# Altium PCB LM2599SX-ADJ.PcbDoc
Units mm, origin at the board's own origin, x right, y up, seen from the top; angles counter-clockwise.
Board outline 62.86 x 68.58 mm, 2 copper layers (TopLayer, BottomLayer); 17 components, 8 nets, 38 pads, 5 vias.
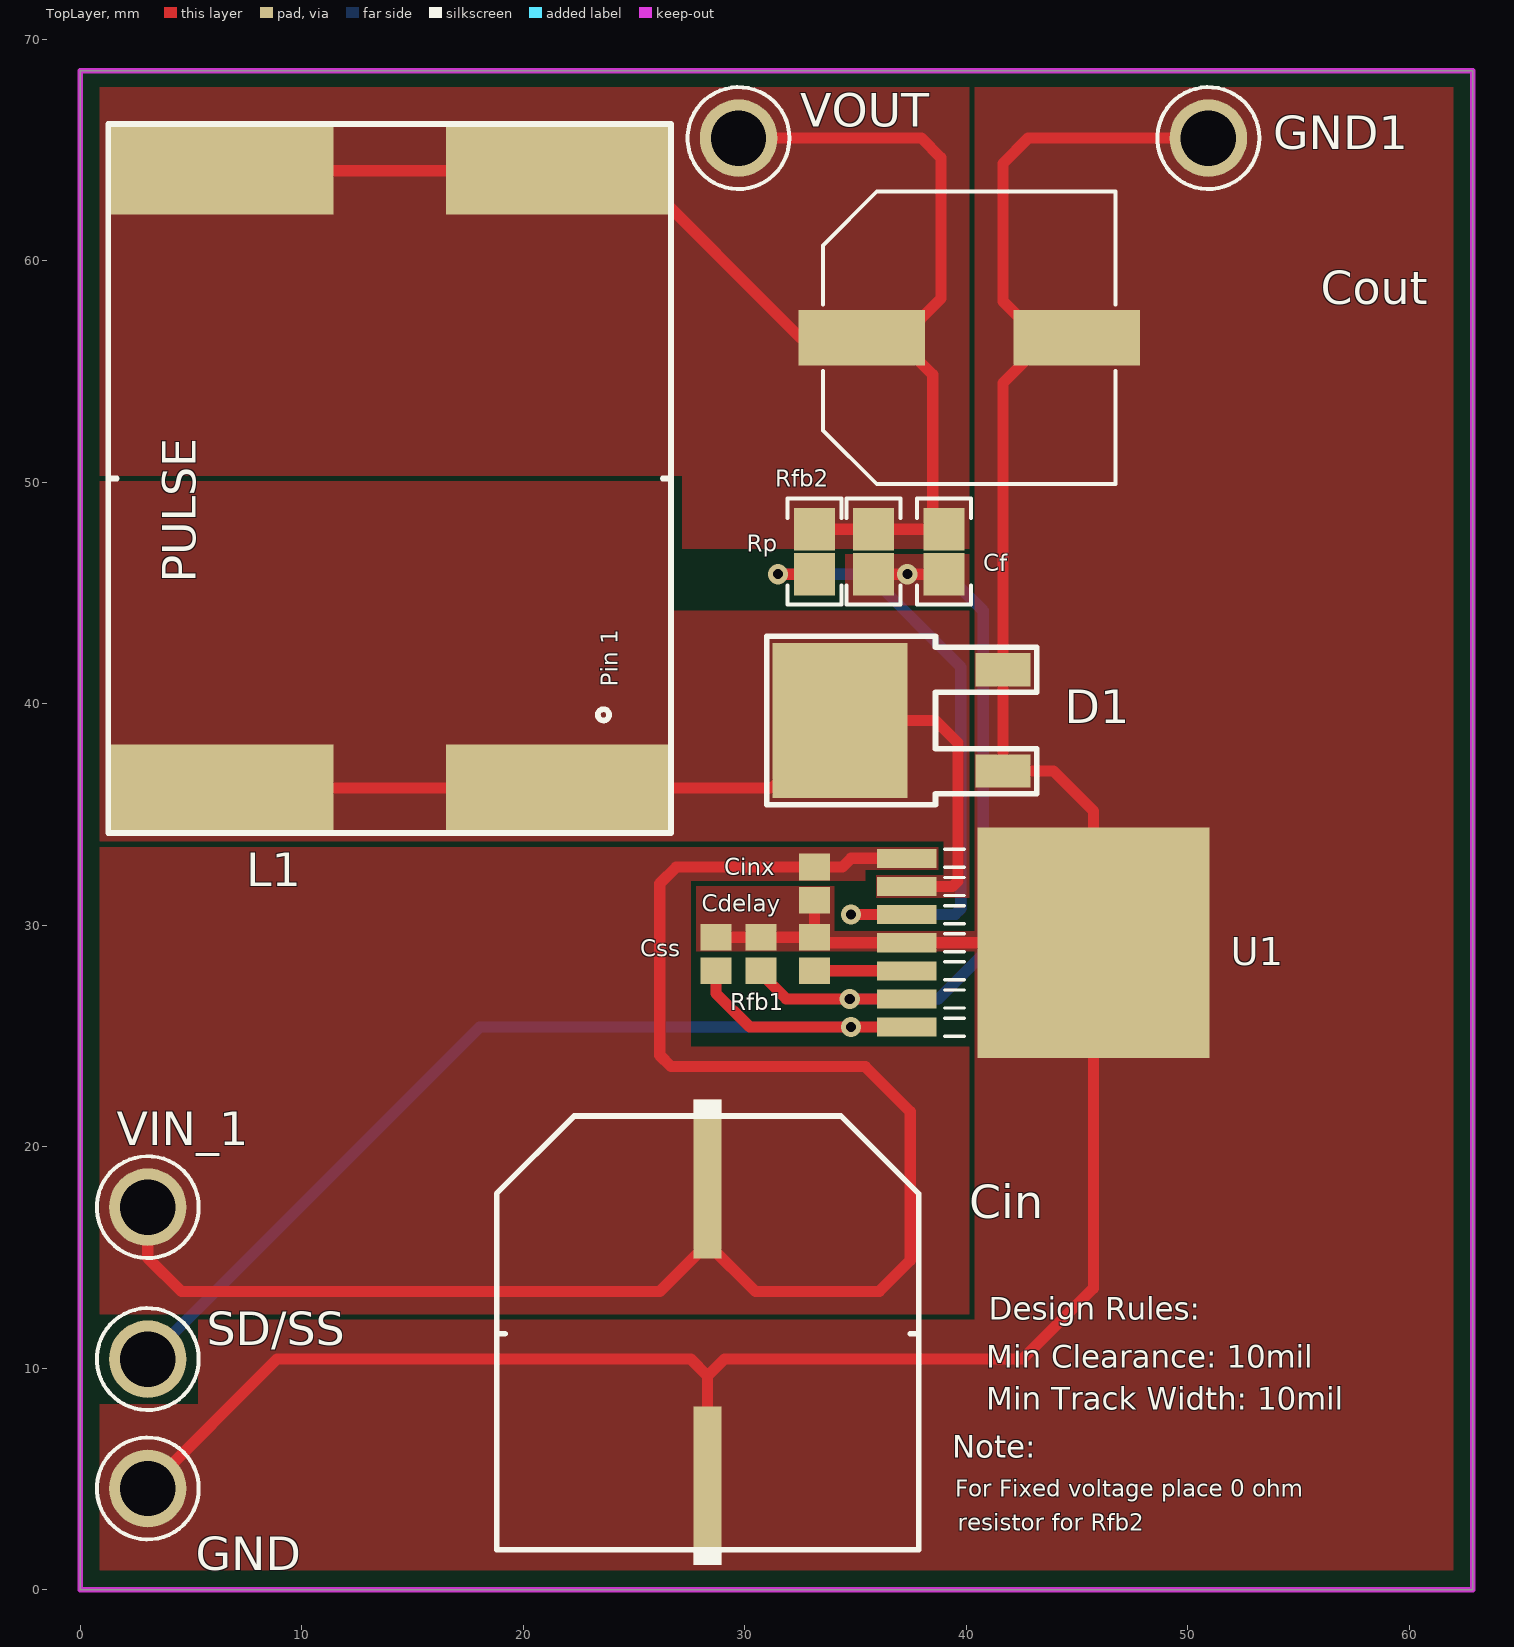
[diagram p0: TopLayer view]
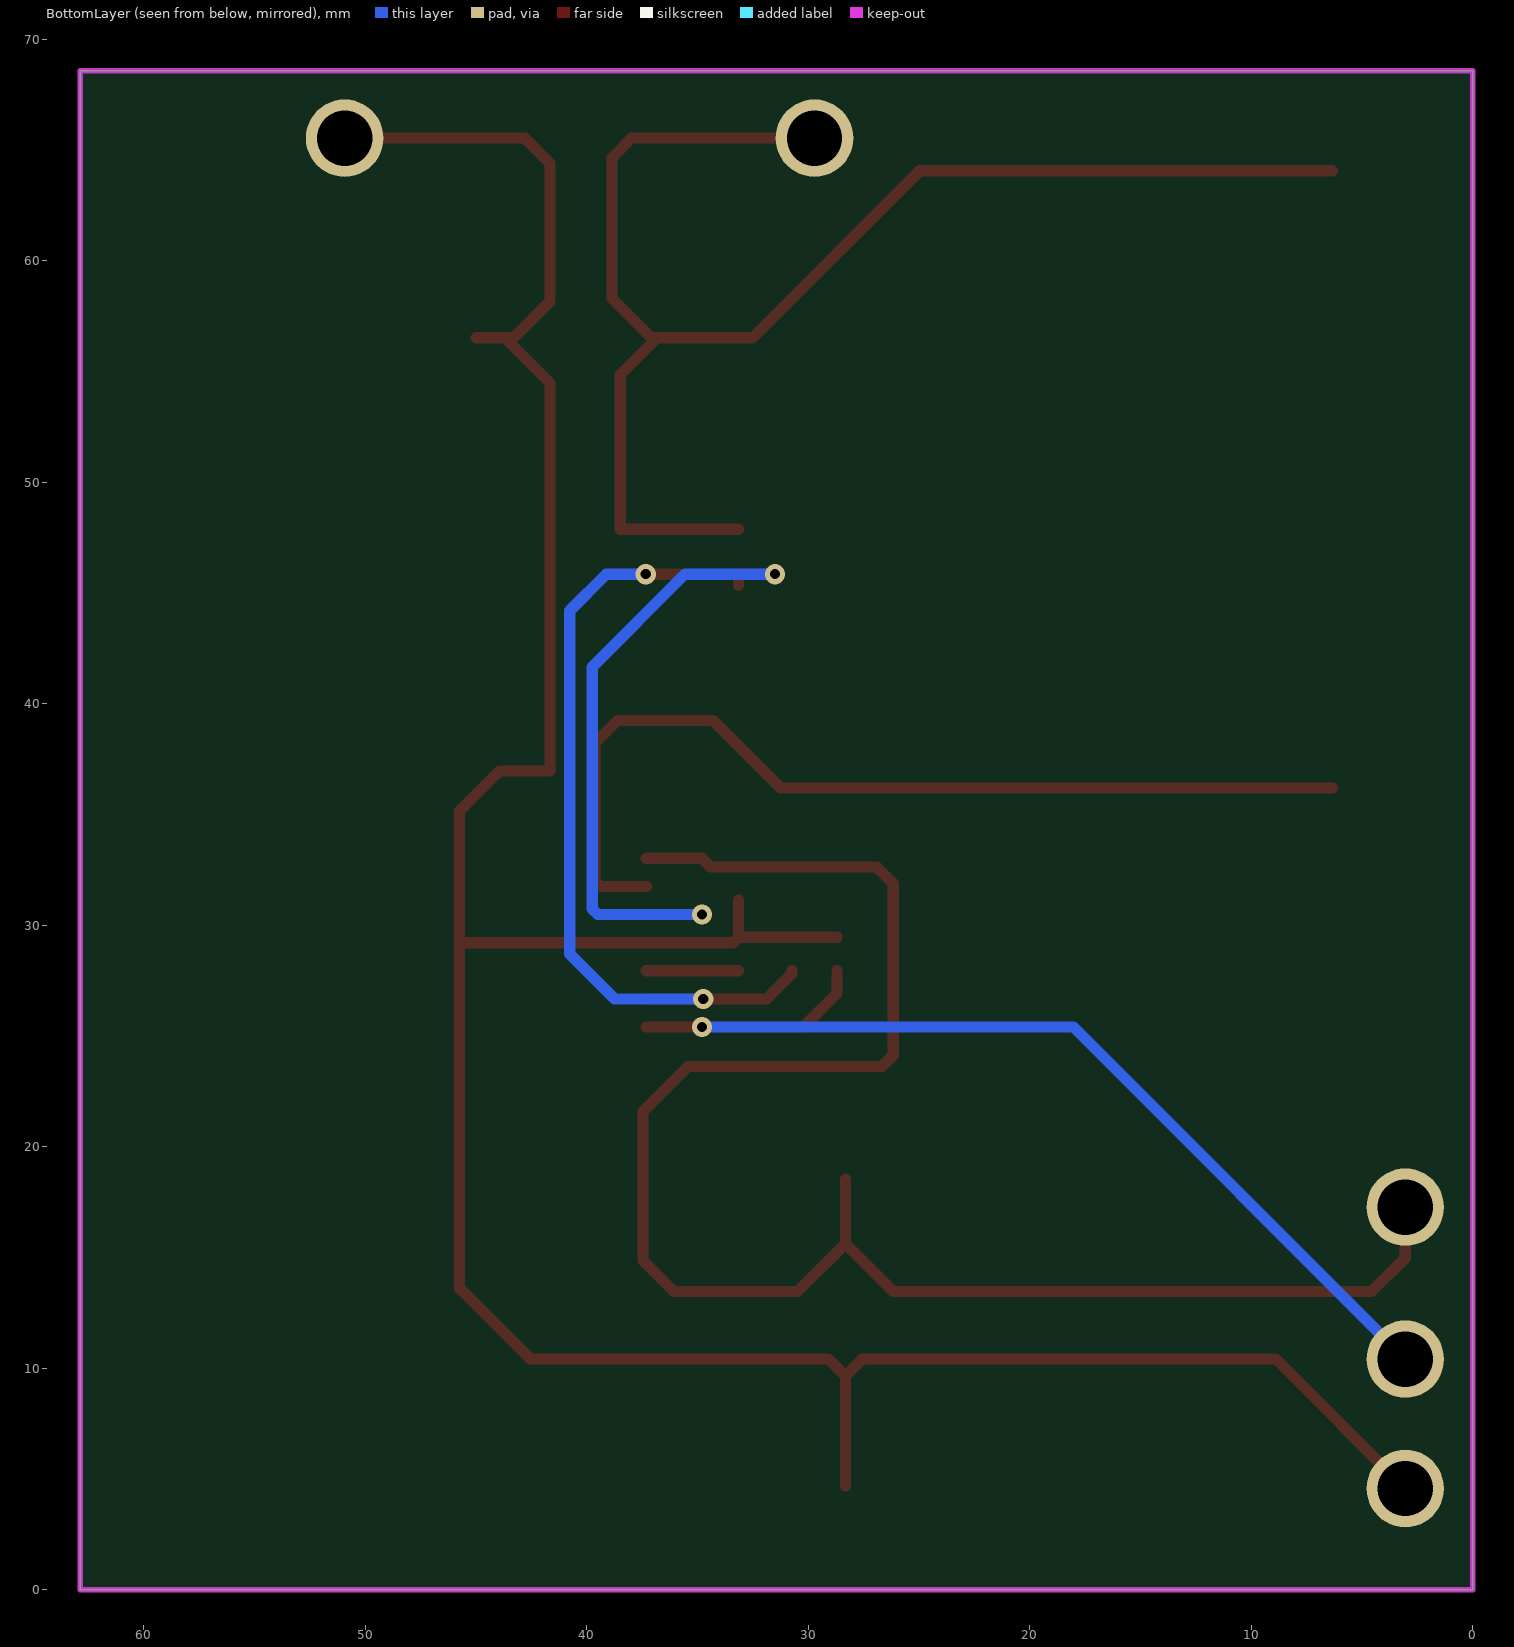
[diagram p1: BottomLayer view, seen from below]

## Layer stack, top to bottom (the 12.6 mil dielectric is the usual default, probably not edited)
TopSolder: solder mask 0.0102, Solder Resist, Dk 3.5
TopLayer: signal copper 0.0356
Dielectric1: core 0.32, FR-4, Dk 4.8
BottomLayer: signal copper 0.0356
BottomSolder: solder mask 0.0102, Solder Resist, Dk 3.5

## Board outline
0,0 0,68.58 62.865,68.58 62.865,0
cut-out: -118.11,-104.14 -117.856,-104.14 -117.856,-103.886 -118.11,-103.886
cut-out: -118.11,-104.14 -117.856,-104.14 -117.856,-103.886 -118.11,-103.886
cut-out: -118.11,-104.14 -117.856,-104.14 -117.856,-103.886 -118.11,-103.886
cut-out: -118.11,-104.14 -117.856,-104.14 -117.856,-103.886 -118.11,-103.886
cut-out: -118.11,-104.14 -117.856,-104.14 -117.856,-103.886 -118.11,-103.886
cut-out: -118.11,-104.14 -117.856,-104.14 -117.856,-103.886 -118.11,-103.886
cut-out: -118.11,-104.14 -117.856,-104.14 -117.856,-103.886 -118.11,-103.886
cut-out: -118.11,-104.14 -117.856,-104.14 -117.856,-103.886 -118.11,-103.886
cut-out: -118.11,-104.14 -117.856,-104.14 -117.856,-103.886 -118.11,-103.886
cut-out: -118.11,-104.14 -117.856,-104.14 -117.856,-103.886 -118.11,-103.886
cut-out: -118.11,-104.14 -117.856,-104.14 -117.856,-103.886 -118.11,-103.886

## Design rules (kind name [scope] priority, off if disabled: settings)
Clearance [All] p1: gap=0.203
PlaneConnect [All] p1: planeconnectstyle=Direct reliefexpansion=0.508 reliefentries=4 reliefconductorwidth=0.254 reliefairgap=0.254
PolygonConnect [All] p1: connectstyle=Direct reliefconductorwidth=0.254 reliefentries=4 polygonreliefangle="90 Angle" airgapwidth=0.254
RoutingVias [All] p1: holewidth=0.711 width=1.27 viastyle="Through Hole" minholewidth=0.711 minwidth=1.27 maxholewidth=0.711 maxwidth=1.27
SolderMaskExpansion [All] p1: expansion=0.102
UnpouredPolygon [All] p1: allowunpoured=FALSE
Width [All] p1: maxlimit=0.508 minlimit=0.051 preferedwidth=0.254
28 further rules are at their usual default settings.

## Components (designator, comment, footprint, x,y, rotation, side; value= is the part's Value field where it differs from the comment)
Cdelay "021A" 0805 33.147,28.702 r90 top
Cf "021A" 1206 38.989,46.863 r90 top (schematic designator Rp)
Cin "021A" CAP-FC-K21 28.321,18.542 r180 top
Cinx "021A" 0805 33.147,31.877 r90 top
Cout "021A" CAPSMT_62_KE0 40.132,56.515 r0 top
Css "021A" 0805 28.702,28.702 r90 top
D1 "021A" DPAK 41.656,36.957 r90 top
GND "Comment" TP-1502 3.048,4.572 r90 top (schematic designator TP6)
GND1 "Comment" TP-1502 50.927,65.532 r0 top (schematic designator TP2)
L1 "021A" PULSE-BIGFOOT 21.59,36.195 r90 top
Rfb1 "021A" 0805 30.734,28.702 r90 top
Rfb2 "021A" 1206 35.814,46.863 r90 top
Rp "021A" 1206 33.147,46.863 r90 top (schematic designator Cf)
SD/SS "Comment" TP-1502 3.048,10.414 r90 top (schematic designator TP5)
U1 "Comment" TS7B 45.593,29.21 r270 top
VIN_1 "Comment" TP-1502 3.048,17.272 r90 top (schematic designator TP3)
VOUT "Comment" TP-1502 29.718,65.532 r0 top (schematic designator TP1)

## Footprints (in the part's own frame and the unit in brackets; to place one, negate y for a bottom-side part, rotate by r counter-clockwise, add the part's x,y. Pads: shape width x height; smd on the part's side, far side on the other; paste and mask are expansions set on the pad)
0805 [mm] "Webench Footprint"
  rect 1.2x1.4 smd: 1(-0.75,0) 2(0.75,0)
  body extent -1.1,-0.72 1.1,0.72, height 1.4
1206 [mm] "Modifed to support 0402 to 08086"
  rect 1.905x1.85 smd: 1(-1.016,0) 2(1.016,0)
  silkscreen extent -2.39,-1.22 2.39,1.22, body extent -1.7,-0.9 1.7,0.9, height 1.35
CAP-FC-K21 [mil]
  rect 50x282 smd: 1(0,0) 2(0,545)
  silkscreen extent -375,-141 375,686
CAPSMT_62_KE0 [mm] "12.5 x 13.5mm:  Chemi-Con KE0"
  rect 5.7x2.5 smd: 1(-4.85,0) 2(4.85,0)
  silkscreen extent -6.6,-6.6 6.6,6.6, body extent -6.6,-6.6 6.6,6.6, height 14
DPAK [mil] "Molded Diode, 2-Leads, Body 4.3x2.6mm, IPC Medium Density, based on OnSemi component dimensions and land pattern"
  rect 59x98 smd: 1(0,0) 3(180,0)
  rect 276x240 smd: 4(90,290)
  silkscreen extent -60,-60 240,420
PULSE-BIGFOOT [mil]
  rect 155x400 smd: 1(0,0) 2(0,600) 3(1097,600) 4(1097,0)
  silkscreen extent -80,-200 1180,800
TP-1502 [mm] "Double Turret"
  round 3.5 hole 2.5: 1(0,0)
  silkscreen extent -2.3,-2.3 2.3,2.3
TS7B [mil]
  rect 34x106 smd: 1(-150,-326) 2(-100,-326) 3(-50,-326) 4(0,-326) 5(50,-326) 6(100,-326) 7(150,-326)
  rect 410x412 smd: 8(0,6)
  silkscreen extent -166,-259 166,-224

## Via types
v1: diameter 0.914, hole 0.457, TopLayer to BottomLayer, 5 vias

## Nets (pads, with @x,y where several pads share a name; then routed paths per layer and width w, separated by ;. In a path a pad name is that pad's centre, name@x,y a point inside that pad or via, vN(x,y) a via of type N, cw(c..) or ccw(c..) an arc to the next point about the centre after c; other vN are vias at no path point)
DELAY: Cdelay.1 U1.5 | length 4.2
  TopLayer w0.508: Cdelay.1 33.159,27.94 U1.5
FB: Cf.1 Rfb1.1 Rfb2.1 U1.6 | length 36.8
  TopLayer w0.508: Rfb1.1 30.734,27.813 31.877,26.67 v1(34.74,26.67) U1.6 ; Rfb2.1 v1(37.338,45.847) Cf.1
  BottomLayer w0.508: v1(34.74,26.67) 38.735,26.67 40.767,28.702 40.767,44.196 39.116,45.847 v1(37.338,45.847)
FLAG: Rp.1 U1.3 | length 30.6
  TopLayer w0.508: v1(31.496,45.847) Rp.1 Rp.1@33.147,45.339 ; v1(34.798,30.48) U1.3
  BottomLayer w0.508: v1(31.496,45.847) 35.56,45.847 39.751,41.656 39.751,30.734 39.497,30.48 v1(34.798,30.48)
GND: Cdelay.2 Cin.2 Cinx.1 Cout.2 Css.2 D1.1 D1.3 GND1.1 GND.1 Rfb1.2 U1.4 U1.8 | length 137.6
  TopLayer w0.508: GND.1 8.89,10.414 27.559,10.414 28.321,9.652 ; Cin.2 28.321,9.652 ; Css.2 Rfb1.2 Cdelay.2 ; Cinx.1 Cdelay.2 ; Cout.2 Cout.2@43.688,56.515 ; GND1.1 42.799,65.532 41.656,64.389 41.656,58.166 43.307,56.515 Cout.2@43.688,56.515 ; 28.321,9.652 29.083,10.414 42.545,10.414 45.745,13.614 U1.8 ; Cdelay.2 33.389,29.21 U1.4 U1.8 ; Cout.2@43.688,56.515 41.656,54.483 D1.3 D1.1 43.942,36.957 45.745,35.154 U1.8
SD/SS: Css.1 SD/SS.1 U1.7 | length 48.2
  TopLayer w0.508: Css.1 28.702,26.924 30.226,25.4 v1(34.798,25.4) U1.7
  BottomLayer w0.508: SD/SS.1 18.034,25.4 v1(34.798,25.4)
SW: D1.4 L1.1 L1.2 U1.2 | length 43.6
  TopLayer w0.508: L1.2 L1.1 31.242,36.195 D1.4 38.608,39.243 39.624,38.227 39.624,32.004 39.37,31.75 U1.2
VIN: Cin.1 Cinx.2 U1.1 VIN_1.1 | length 81.1
  TopLayer w0.508: VIN_1.1 3.048,14.986 4.572,13.462 26.162,13.462 Cin.1@28.321,15.621 ; Cin.1 Cin.1@28.321,15.621 ; U1.1 34.798,33.02 34.405,32.627 Cinx.2 26.912,32.627 26.162,31.877 26.162,24.13 26.67,23.622 35.433,23.622 37.465,21.59 37.465,14.859 36.068,13.462 30.48,13.462 Cin.1@28.321,15.621
VOUT: Cf.2 Cout.1 L1.3 L1.4 Rfb2.2 Rp.2 VOUT.1 | length 65.1
  TopLayer w0.508: L1.3 L1.4 24.968,64.059 32.512,56.515 Cout.1 Cout.1@36.83,56.515 ; 31.496,65.532 37.973,65.532 38.862,64.643 38.862,58.293 37.084,56.515 Cout.1@36.83,56.515 ; Rp.2 Rfb2.2 38.481,47.879 38.481,54.864 Cout.1@36.83,56.515

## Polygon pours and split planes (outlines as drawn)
FB on TopLayer "TopLayer-FB" (solid, remove dead copper, pour order 16): 34.544,46.736 34.544,44.45 40.132,44.45 40.132,46.736
GND on TopLayer "TopLayer-GND" (solid, remove dead copper, pour order 14): 40.386,12.192 5.334,12.192 5.334,8.382 0.889,8.382 0.889,0.889 61.976,0.889 61.976,67.818 40.386,67.818 40.386,29.718 34.036,29.718 34.036,31.75 27.813,31.75 27.813,28.829 32.004,28.829 40.386,28.829
VOUT on TopLayer "TopLayer-VOUT" (solid, remove dead copper, pour order 10): 0.889,50.292 27.178,50.292 27.178,46.99 40.132,46.99 40.132,67.818 0.889,67.818
SW on TopLayer "TopLayer-SW" (solid, remove dead copper, pour order 4): 35.941,32.258 35.941,31.242 40.132,31.242 40.132,44.196 26.797,44.196 26.797,50.038 0.889,50.038 0.889,43.434 0.889,33.782 38.989,33.782 38.989,32.258
VIN on TopLayer "TopLayer-VIN" (solid, remove dead copper, pour order 2): 38.735,33.528 38.735,32.512 35.433,32.512 35.433,32.004 27.559,32.004 27.559,24.511 40.132,24.511 40.132,12.446 0.889,12.446 0.889,33.528

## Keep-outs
KeepOutLayer:
  the board outline again, w0.254

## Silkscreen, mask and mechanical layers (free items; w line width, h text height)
TopOverlay:
  text "Design Rules:" at 41.021,12.192 h1.02
  text "Min Clearance: 10mil" at 40.894,10.033 h1.02
  text "Min Track Width: 10mil" at 40.894,8.128 h1.02
  text "Note:" at 39.37,5.969 h1.02
  text "For Fixed voltage place 0 ohm" at 39.497,4.191 h0.76
  text "resistor for Rfb2" at 39.624,2.667 h0.76
Mechanical1:
  the board outline again, w0.254

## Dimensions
62.865,0 to 62.865,68.58 on Mechanical1
0,0 to 62.865,0 on Mechanical1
